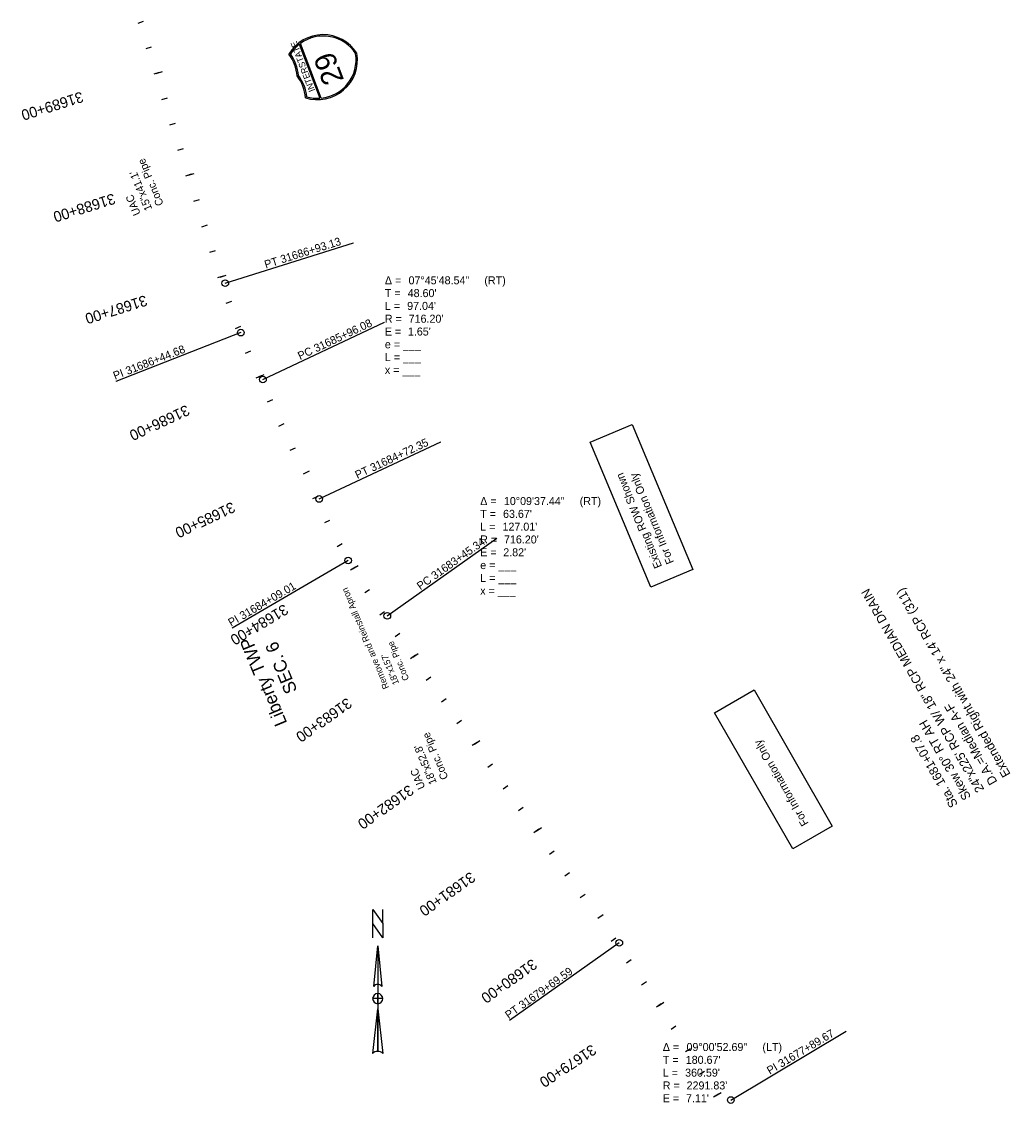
# Model space of a CAD drawing. Extents: x 14087837 to 14090046, y 8544369 to 8548535.
# Drawn here: x 14088665 to 14089592, y 8545388 to 8546402 of the extents above; entities that cross this region are included whole.
import ezdxf

# ---------------------------------------------------------------- set-up
doc = ezdxf.new("R2010")
doc.units = 0
for name, color, linetype in [('_CIVIL_CONSTRUCTION', 7, 'Continuous'), ('Default', 7, 'Continuous'), ('EXT_SNP', 7, 'Continuous'), ('Roadways', 7, 'Continuous'), ('TextAlignment', 7, 'Continuous'), ('Wetlands', 7, 'Continuous')]:
    doc.layers.add(name, color=color, linetype=linetype)

msp = doc.modelspace()

# ---------------------------------------------------------------- linework, layer by layer
at = {"layer": '_CIVIL_CONSTRUCTION'}
for p, q in [((14088855.7, 8546157.1), (14088976, 8546194.9)), ((14088976, 8546194.9), (14088976, 8546194.9)), ((14088891, 8546066.8), (14089005, 8546120.4)), ((14089005, 8546120.4), (14089005, 8546120.4)), ((14088870.3, 8546110.7), (14088752.9, 8546064.9)), ((14088752.9, 8546064.9), (14088752.9, 8546064.9)), ((14088943.7, 8545954.8), (14089057.7, 8546008.5)), ((14089057.7, 8546008.5), (14089057.7, 8546008.5)), ((14089007.6, 8545845.3), (14089110.4, 8545918.2)), ((14089110.4, 8545918.2), (14089110.4, 8545918.2)), ((14088970.8, 8545897.2), (14088862, 8545833.7)), ((14088862, 8545833.7), (14088862, 8545833.7)), ((14089225.1, 8545538.8), (14089122.3, 8545465.9)), ((14089122.3, 8545465.9), (14089122.3, 8545465.9)), ((14089329.6, 8545391.5), (14089437.8, 8545456.1)), ((14089437.8, 8545456.1), (14089437.8, 8545456.1))]:
    msp.add_line(p, q, dxfattribs=at)
for centre in [(14088855.7, 8546157.1), (14088870.3, 8546110.7), (14088891, 8546066.8), (14088943.7, 8545954.8), (14088970.8, 8545897.2), (14089007.6, 8545845.3), (14089225.1, 8545538.8), (14089329.6, 8545391.5)]:
    msp.add_circle(centre, 3.12, dxfattribs=at)
at = {"layer": 'EXT_SNP'}
for p, q in [((14088925.1, 8546381), (14088944.3, 8546330.3)), ((14088945.6, 8546330.4), (14088926.2, 8546381.8)), ((14088998.6, 8545535.9), (14089002.4, 8545497.9)), ((14088998.6, 8545535.9), (14088998.6, 8545437.1)), ((14088994.8, 8545497.9), (14088994.8, 8545497.9)), ((14088995, 8545498.3), (14088995.7, 8545499.1)), ((14088993.9, 8545435.2), (14088998.6, 8545477)), ((14088998.6, 8545481.8), (14088998.6, 8545481.8))]:
    msp.add_line(p, q, dxfattribs=at)
for points in [[(14089254.6, 8545872.1), (14089197.9, 8546008.2), (14089237.3, 8546024.6), (14089294, 8545888.6)], [(14089387.8, 8545626.8), (14089314.4, 8545754.5), (14089351.4, 8545775.8), (14089424.8, 8545648)], [(14089003.4, 8545543.6), (14088993.9, 8545556.9), (14088993.9, 8545570.2), (14089003.4, 8545556.9)]]:
    msp.add_lwpolyline(points, close=True, dxfattribs=at)
for points in [[(14088993.9, 8545543.6), (14088993.9, 8545570.2), (14089003.4, 8545556.9), (14089003.4, 8545570.2)], [(14088994.8, 8545497.9), (14088998.6, 8545535.9), (14088998.6, 8545499.8)], [(14088998.6, 8545481.8), (14088998.6, 8545486.5), (14088993.9, 8545486.5)], [(14089003.4, 8545486.5), (14088998.6, 8545486.5), (14088998.6, 8545491.3)], [(14088998.6, 8545437.1), (14088998.6, 8545477), (14089003.4, 8545435.2)]]:
    msp.add_lwpolyline(points, dxfattribs=at)
for centre, radius, start, end in [((14088947.4, 8546352.5), 37.5, 32.262, 149.056), ((14088947.5, 8546352.5), 36.2, 32.6545, 125.9715), ((14088947.4, 8546352.5), 36.2, 127.9881, 147.729), ((14088885.6, 8546348.8), 37.5, 3.7339, 37.716), ((14088885.5, 8546348.9), 38.8, 4.1504, 36.2859), ((14088942.1, 8546366.5), 37.5, 252.3938, 9.1879), ((14088942.1, 8546366.5), 36.2, 275.4783, 8.7954), ((14088893.4, 8546328.3), 37.5, 3.7339, 37.716), ((14088893.4, 8546328.2), 38.8, 5.164, 37.2995), ((14088942.1, 8546366.5), 36.2, 253.7208, 273.4615), ((14088998.6, 8545495.1), 4.75, 90.0204, 143.1257), ((14088998.6, 8545495.1), 4.75, 36.8481, 90.0218), ((14088998.6, 8545486.5), 4.75, 90, 180), ((14088998.6, 8545486.5), 4.75, 180, 270), ((14088998.6, 8545486.5), 4.75, 0, 90), ((14088998.6, 8545486.5), 4.75, 270, 360), ((14088998.6, 8545430.2), 6.89, 89.9894, 133.619), ((14088998.6, 8545430.2), 6.89, 46.4021, 90.0006)]:
    msp.add_arc(centre, radius, start, end, dxfattribs=at)
at = {"layer": 'Roadways'}
for p, q in [((14088778.8, 8546402.2), (14088773.6, 8546400.5)), ((14088786.3, 8546378.3), (14088781.1, 8546376.7)), ((14088790.8, 8546353.6), (14088796.7, 8546355.4)), ((14088801.3, 8546330.6), (14088796, 8546329)), ((14088808.7, 8546306.8), (14088803.5, 8546305.1)), ((14088816.2, 8546282.9), (14088811, 8546281.3)), ((14088820.8, 8546258.2), (14088826.6, 8546260)), ((14088831.2, 8546235.2), (14088826, 8546233.6)), ((14088838.7, 8546211.4), (14088833.5, 8546209.7)), ((14088846.2, 8546187.5), (14088841, 8546185.9)), ((14088850.8, 8546162.7), (14088856.6, 8546164.6)), ((14088861.4, 8546139.9), (14088856.2, 8546138.1)), ((14088869.9, 8546116.4), (14088864.8, 8546114.4)), ((14088879.2, 8546093.2), (14088874.2, 8546091.1)), ((14088886.6, 8546069), (14088892.1, 8546071.6)), ((14088900, 8546047.7), (14088895, 8546045.4)), ((14088910.6, 8546025.1), (14088905.7, 8546022.7)), ((14088921.3, 8546002.4), (14088916.3, 8546000.1)), ((14088929.1, 8545978.5), (14088934.7, 8545981.1)), ((14088942.5, 8545957.2), (14088937.6, 8545954.9)), ((14088953.5, 8545934.7), (14088948.6, 8545932.3)), ((14088965.2, 8545912.7), (14088960.5, 8545910)), ((14088975.1, 8545889.4), (14088980.3, 8545892.6)), ((14088991, 8545869.8), (14088986.4, 8545866.8)), ((14089004.9, 8545849.1), (14089000.5, 8545845.9)), ((14089019.4, 8545828.7), (14089014.9, 8545825.5)), ((14089031.4, 8545806.5), (14089036.4, 8545810.1)), ((14089048.3, 8545787.9), (14089043.9, 8545784.7)), ((14089062.8, 8545767.5), (14089058.3, 8545764.4)), ((14089077.3, 8545747.1), (14089072.8, 8545744)), ((14089089.2, 8545725), (14089094.2, 8545728.5)), ((14089106.2, 8545706.3), (14089101.7, 8545703.2)), ((14089120.7, 8545686), (14089116.2, 8545682.8)), ((14089135.1, 8545665.6), (14089130.7, 8545662.4)), ((14089147.1, 8545643.4), (14089152.1, 8545646.9)), ((14089164.1, 8545624.8), (14089159.6, 8545621.6)), ((14089178.5, 8545604.4), (14089174.1, 8545601.2)), ((14089193, 8545584), (14089188.5, 8545580.9)), ((14089205, 8545561.9), (14089210, 8545565.4)), ((14089221.9, 8545543.2), (14089217.5, 8545540.1)), ((14089236.3, 8545522.8), (14089231.8, 8545519.7)), ((14089250.5, 8545502.2), (14089246, 8545499.1)), ((14089261.9, 8545479.8), (14089267, 8545483.2)), ((14089278.2, 8545460.6), (14089273.6, 8545457.6)), ((14089291.7, 8545439.5), (14089287.1, 8545436.6)), ((14089305, 8545418.3), (14089300.3, 8545415.5)), ((14089315.4, 8545395.4), (14089320.6, 8545398.6))]:
    msp.add_line(p, q, dxfattribs=at)
at = {"layer": 'Wetlands'}
for p, q in [((14088793.8, 8546354.5), (14088788.6, 8546352.8)), ((14088823.7, 8546259.1), (14088818.5, 8546257.4)), ((14088853.7, 8546163.7), (14088848.5, 8546162)), ((14088889.3, 8546070.3), (14088884.4, 8546068)), ((14088929.1, 8545978.5), (14088934.7, 8545981.1)), ((14088977.7, 8545891), (14088973, 8545888.2)), ((14089033.9, 8545808.3), (14089029.4, 8545805.1)), ((14089091.7, 8545726.7), (14089087.3, 8545723.6)), ((14089149.6, 8545645.2), (14089145.1, 8545642)), ((14089205, 8545561.9), (14089210, 8545565.4)), ((14089264.5, 8545481.5), (14089259.9, 8545478.4)), ((14089318, 8545397), (14089313.3, 8545394.2))]:
    msp.add_line(p, q, dxfattribs=at)

# ---------------------------------------------------------------- texts
at = {"layer": '_CIVIL_CONSTRUCTION'}
for s, rotation, p in [('31686+93.13', 17.4334, (14088908.7, 8546175.5)), ('PT', 17.4334, (14088893.7, 8546170.7)), ('Δ = ', 360, (14089005.3, 8546156)), ('07°45\'48.54"', 360, (14089027.5, 8546156)), (' (RT)', 360, (14089095.8, 8546156)), ('T = ', 360, (14089005.3, 8546144)), ("48.60'", 360, (14089026.7, 8546144)), ('L = ', 360, (14089005.3, 8546132)), ("97.04'", 360, (14089026.2, 8546132)), ('31685+96.08', 25.1969, (14088940.9, 8546092.1)), ('R = ', 360, (14089005.3, 8546120)), ("716.20'", 360, (14089027.6, 8546120)), ('E = ', 360, (14089005.3, 8546108)), ("1.65'", 360, (14089026.9, 8546108)), ('e = ___ ', 360, (14089005.3, 8546096)), ('31686+44.68', 21.3152, (14088764, 8546071)), ('PC', 25.1969, (14088925.8, 8546085)), ('L = ___', 360, (14089005.3, 8546084)), ('PI ', 21.3152, (14088752.3, 8546066.5)), ('x = ___', 360, (14089005.3, 8546072)), ('31684+72.35', 25.1969, (14088993.7, 8545980.2)), ('PT', 25.1969, (14088979.5, 8545973.5)), ('31683+45.34', 35.3573, (14089052.1, 8545878.9)), ('PC', 35.3573, (14089038.6, 8545869.2)), ('31684+09.01', 30.2771, (14088871.9, 8545841.4)), ('PI ', 30.2771, (14088861.1, 8545835.1)), ('31679+69.59', 35.3573, (14089134.2, 8545476.4)), ('PT', 35.3573, (14089121.3, 8545467.2)), ('31677+89.67', 30.85, (14089376.9, 8545421.6)), ('PI ', 30.85, (14089366.2, 8545415.2))]:
    msp.add_text(s, height=7.5, rotation=rotation, dxfattribs=at).set_placement(p)
for s, p in [('Δ = ', (14089094.7, 8545949.1)), ('10°09\'37.44"', (14089116.9, 8545949.1)), (' (RT)', (14089185.2, 8545949.1)), ('T = ', (14089094.7, 8545937.1)), ("63.67'", (14089116.1, 8545937.1)), ('L = ', (14089094.7, 8545925.1)), ("127.01'", (14089115.6, 8545925.1)), ('R = ', (14089094.7, 8545913.1)), ("716.20'", (14089117, 8545913.1)), ("2.82'", (14089116.3, 8545901.1)), ('E = ', (14089094.7, 8545901.1)), ('e = ___ ', (14089094.7, 8545889.1)), ('L = ___', (14089094.7, 8545877.1)), ('x = ___', (14089094.7, 8545865.1)), ('Δ = ', (14089265.9, 8545437.4)), ('09°00\'52.69"', (14089288.1, 8545437.4)), (' (LT)', (14089356.5, 8545437.4)), ('T = ', (14089265.9, 8545425.4)), ("180.67'", (14089287.4, 8545425.4)), ('L = ', (14089265.9, 8545413.4)), ("360.59'", (14089286.8, 8545413.4)), ('R = ', (14089265.9, 8545401.4)), ("2291.83'", (14089288.2, 8545401.4)), ('E = ', (14089265.9, 8545389.4)), ("7.11'", (14089287.6, 8545389.4))]:
    msp.add_text(s, height=7.5, dxfattribs=at).set_placement(p)
at = {"layer": 'Default'}
for s, rotation, p in [('Existing ROW Shown', 112.6265, (14089265.3, 8545891.6)), ('For Information Only', 112.6265, (14089276.6, 8545895.6)), ('For Information Only', 119.8939, (14089402.9, 8545650.8))]:
    msp.add_text(s, height=7.5, rotation=rotation, dxfattribs=at).set_placement(p)
at = {"layer": 'EXT_SNP'}
for s, height, p in [('INTERSTATE', 6, (14088940, 8546337.7)), ('29', 20, (14088967.2, 8546347.5))]:
    msp.add_text(s, height=height, rotation=110.7249, dxfattribs=at).set_placement(p)
at = {"layer": 'Roadways'}
for s, rotation, p in [('31689+00', 197.4334, (14088720.7, 8546336.8)), ('31688+00', 197.4334, (14088750.7, 8546241.4)), ('31687+00', 197.4334, (14088780.6, 8546146)), ('31686+00', 204.8836, (14088819.2, 8546043.3)), ('31685+00', 205.1969, (14088861.9, 8545952.4)), ('31684+00', 210.9849, (14088910.8, 8545856.7)), ('31683+00', 215.3573, (14088969.8, 8545769)), ('31682+00', 215.3573, (14089027.7, 8545687.4)), ('31681+00', 215.3573, (14089085.5, 8545605.9)), ('31680+00', 215.3573, (14089143.4, 8545524.3)), ('31679+00', 213.6177, (14089199.2, 8545444.1))]:
    msp.add_text(s, height=10.02, rotation=rotation, dxfattribs=at).set_placement(p)
at = {"layer": 'TextAlignment'}
for s, height, rotation, p in [('Conc. Pipe', 7.2, 112.6265, (14088798, 8546231.2)), ('15"x41.1\'', 7.2, 112.6265, (14088787.3, 8546226.7)), ('UAC', 7.2, 112.6265, (14088776.5, 8546222.2)), ('Remove and Reinstall Apron', 6, 112.6265, (14089009.4, 8545778.1)), ('24"x225\' RCP W/ 18" RCP MEDIAN DRAIN', 8.4, 119.8939, (14089567.5, 8545682.7)), ('Extended Right with 24" x 14\' RCP (311)', 8.4, 119.8939, (14089592.2, 8545696.9)), ('Liberty TWP.', 12, 112.6265, (14088913.9, 8545744.9)), ('SEC. 6', 12, 112.6265, (14088923.4, 8545775.3)), ('Conc. Pipe', 6, 112.6265, (14089028.2, 8545786)), ('18"x157\'', 6, 112.6265, (14089018.8, 8545782.1)), ('D.A.=Median A-F', 8.4, 119.8939, (14089579.8, 8545689.7)), ('Skew 30° RT AH', 8.4, 119.8939, (14089555.1, 8545675.5)), ('Conc. Pipe', 7.2, 112.6265, (14089064.9, 8545693.5)), ('Sta. 1681+07.8', 8.4, 119.8939, (14089542.8, 8545668.5)), ('18"x52.8\'', 7.2, 112.6265, (14089054.1, 8545688.9)), ('UAC', 7.2, 112.6265, (14089043.3, 8545684.4))]:
    msp.add_text(s, height=height, rotation=rotation, dxfattribs=at).set_placement(p)
at = {"layer": 'Wetlands'}
for s, rotation, p in [('31685+00', 205.1969, (14088861.9, 8545952.4)), ('31680+00', 215.3573, (14089143.4, 8545524.3))]:
    msp.add_text(s, height=10.02, rotation=rotation, dxfattribs=at).set_placement(p)

doc.saveas('drawing.dxf')
